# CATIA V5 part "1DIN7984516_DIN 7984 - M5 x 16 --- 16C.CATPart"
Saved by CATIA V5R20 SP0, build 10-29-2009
Part number: 1DIN7984516_DIN 7984 - M5 x 16 --- 16C
Revision: ANY
Definition: UNKNOWN
Nomenclature: 1DIN7984516_DIN 7984 - M5 x 16 --- 16C
Source: Unknown
Bounding box of the stored display mesh (mm): x 0 to 19.5, y -4.25 to 4.25, z -4.25 to 4.25
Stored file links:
  C:\Users\Utente\Desktop\IO LAVORO\3D X SITO CF\CUMSA\3D files PW\pw081225\pw081225_ejection\1DIN7984516_DIN 7984 - M5 x 16 --- 16C.CATPart
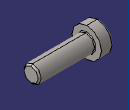
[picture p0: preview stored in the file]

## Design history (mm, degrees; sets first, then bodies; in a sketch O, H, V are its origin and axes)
Body1 "Hex" (main body)
  Solid1: solid without history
